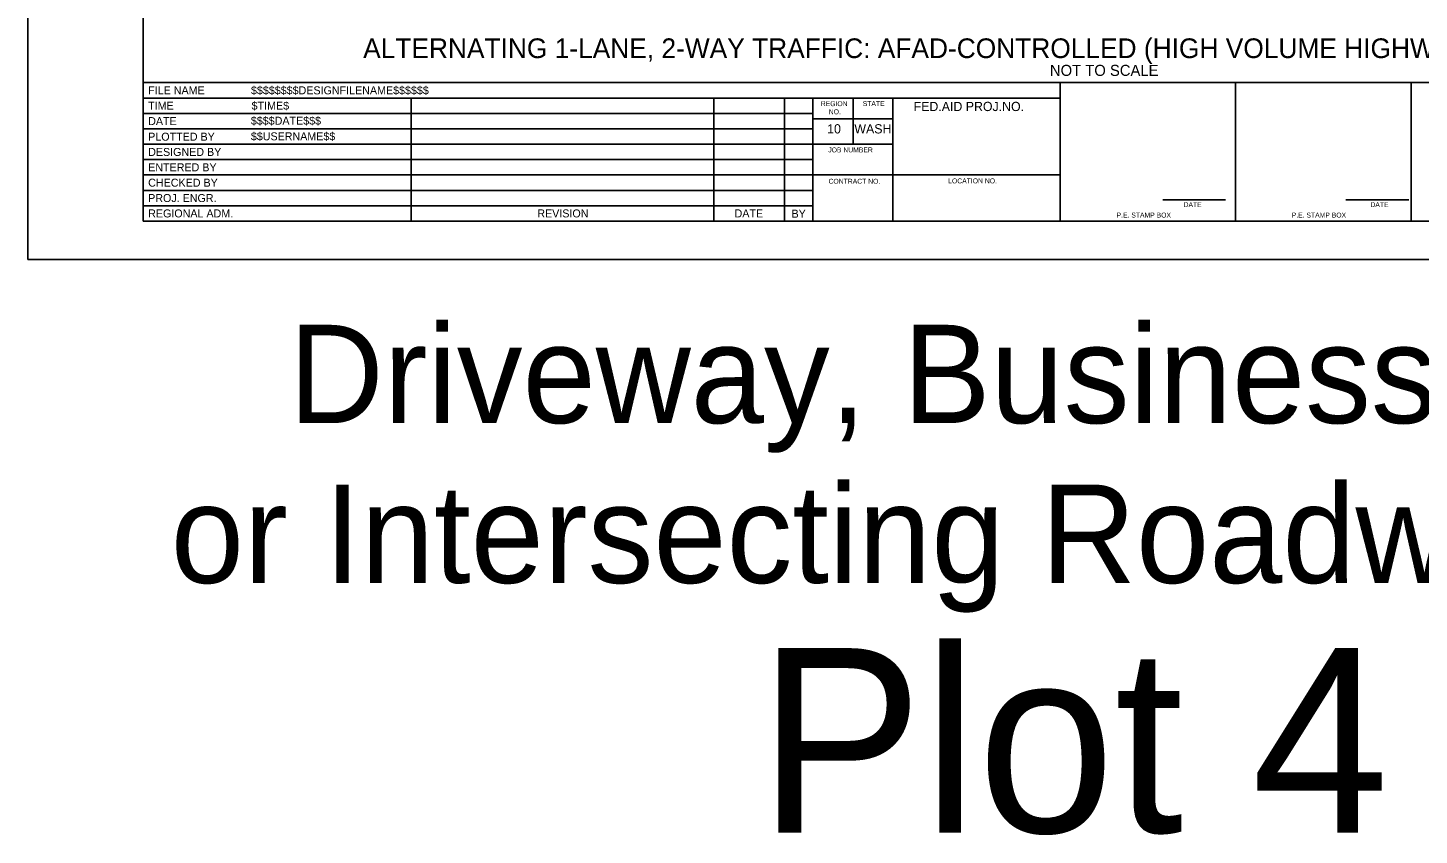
# Model space of a CAD drawing. Extents: x 99999.1 to 100095.7, y 99995 to 100010.7.
# Drawn here: x 100059.06 to 100070.38, y 99995.01 to 100001.57 of the extents above; entities that cross this region are included whole.
import ezdxf

# ---------------------------------------------------------------- set-up
doc = ezdxf.new("R2010")
doc.units = 0
for name, color, linetype in [('SH_DE_DetailHeading1Text', 7, 'Continuous'), ('SH_GI_PlotLimits', 7, 'Continuous'), ('SH_GI_SheetBorder', 7, 'Continuous'), ('SH_GI_SheetLocationText', 7, 'Continuous'), ('SH_GI_SheetTextInCells', 7, 'Continuous'), ('SH_GI_TitleBlockText', 7, 'Continuous')]:
    doc.layers.add(name, color=color, linetype=linetype)

msp = doc.modelspace()

# ---------------------------------------------------------------- linework, layer by layer
at = {"layer": 'SH_GI_PlotLimits'}
msp.add_lwpolyline([(100059.062, 99999.687), (100076.062, 99999.687), (100076.062, 100010.687), (100059.062, 100010.687)], close=True, dxfattribs=at)
at = {"layer": 'SH_GI_SheetBorder'}
for p, q in [((100060, 100010.375), (100060, 100000)), ((100060, 100001.126), (100075.75, 100001.126)), ((100067.457, 100000), (100067.457, 100001.126)), ((100068.883, 100000), (100068.883, 100001.126)), ((100070.309, 100001.126), (100070.309, 100000)), ((100060, 100001.001), (100067.457, 100001.001)), ((100062.179, 100001.001), (100062.179, 100000)), ((100064.641, 100001.001), (100064.641, 100000)), ((100065.216, 100001.001), (100065.216, 100000)), ((100065.445, 100001.001), (100065.445, 100000)), ((100065.772, 100000.625), (100065.772, 100001.001)), ((100066.096, 100000), (100066.096, 100001.001)), ((100060, 100000.876), (100062.182, 100000.876)), ((100062.182, 100000.876), (100065.447, 100000.876)), ((100066.096, 100000.831), (100065.447, 100000.831)), ((100060, 100000.751), (100062.182, 100000.751)), ((100062.182, 100000.751), (100065.447, 100000.751)), ((100060, 100000.625), (100065.447, 100000.625)), ((100066.096, 100000.625), (100065.447, 100000.625)), ((100060, 100000.5), (100065.447, 100000.5)), ((100060, 100000.375), (100065.447, 100000.375)), ((100067.457, 100000.375), (100065.447, 100000.375)), ((100060, 100000.25), (100065.447, 100000.25)), ((100060, 100000.125), (100065.447, 100000.125)), ((100068.29, 100000.173), (100068.802, 100000.173)), ((100069.78, 100000.173), (100070.291, 100000.173)), ((100060, 100000), (100075.75, 100000))]:
    msp.add_line(p, q, dxfattribs=at)

# ---------------------------------------------------------------- texts
at = {"layer": 'SH_DE_DetailHeading1Text'}
for s, height, p in [('ALTERNATING 1-LANE, 2-WAY TRAFFIC: AFAD-CONTROLLED (HIGH VOLUME HIGHWAYS, 40 MPH OR LESS)', 0.16, (100061.789, 100001.326)), ('NOT TO SCALE', 0.09, (100067.373, 100001.181))]:
    msp.add_text(s, height=height, rotation=360, dxfattribs=at).set_placement(p)
at = {"layer": 'SH_GI_SheetLocationText'}
for s, height, p in [('Driveway, Business Access,', 0.8, (100061.184, 99998.357)), ('or Intersecting Roadway Details', 0.8, (100060.225, 99997.057)), ('Plot 4', 1.5, (100065.001, 99995.027))]:
    msp.add_text(s, height=height, dxfattribs=at).set_placement(p)
at = {"layer": 'SH_GI_SheetTextInCells'}
for s, height, p in [('FILE NAME', 0.0651, (100060.041, 100001.031)), ('TIME', 0.0651, (100060.041, 100000.906)), ('REGION', 0.04, (100065.51, 100000.935)), ('NO.', 0.04, (100065.575, 100000.869)), ('STATE', 0.04, (100065.851, 100000.936)), ('FED.AID PROJ.NO.', 0.07506, (100066.265, 100000.895)), ('DATE', 0.0651, (100060.041, 100000.781)), ('10', 0.0751, (100065.562, 100000.713)), ('WASH', 0.0751, (100065.783, 100000.713)), ('PLOTTED BY', 0.0651, (100060.041, 100000.654)), ('DESIGNED BY', 0.06505, (100060.041, 100000.53)), ('JOB NUMBER', 0.04, (100065.571, 100000.559)), ('ENTERED BY', 0.0651, (100060.041, 100000.405)), ('CHECKED BY', 0.0651, (100060.041, 100000.28)), ('CONTRACT NO.', 0.04003, (100065.573, 100000.304)), ('LOCATION NO.', 0.04003, (100066.546, 100000.307)), ('PROJ. ENGR.', 0.06505, (100060.041, 100000.155)), ('REGIONAL ADM.', 0.06505, (100060.041, 100000.03)), ('REVISION', 0.0651, (100063.205, 100000.03)), ('DATE', 0.04, (100068.46, 100000.114)), ('DATE', 0.04, (100069.979, 100000.114)), ('DATE', 0.0651, (100064.809, 100000.03)), ('BY', 0.0651, (100065.272, 100000.028)), ('P.E. STAMP BOX', 0.04003, (100067.915, 100000.029)), ('P.E. STAMP BOX', 0.04003, (100069.339, 100000.029))]:
    msp.add_text(s, height=height, dxfattribs=at).set_placement(p)
at = {"layer": 'SH_GI_TitleBlockText'}
for s, height, p in [('$$$$$$$$DESIGNFILENAME$$$$$$', 0.06505, (100060.877, 100001.031)), ('$TIME$', 0.0651, (100060.882, 100000.906)), ('$$$$DATE$$$', 0.06505, (100060.876, 100000.784)), ('$$USERNAME$$', 0.06505, (100060.876, 100000.657))]:
    msp.add_text(s, height=height, dxfattribs=at).set_placement(p)

doc.saveas('drawing.dxf')
